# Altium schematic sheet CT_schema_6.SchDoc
size 479 x 328 mm
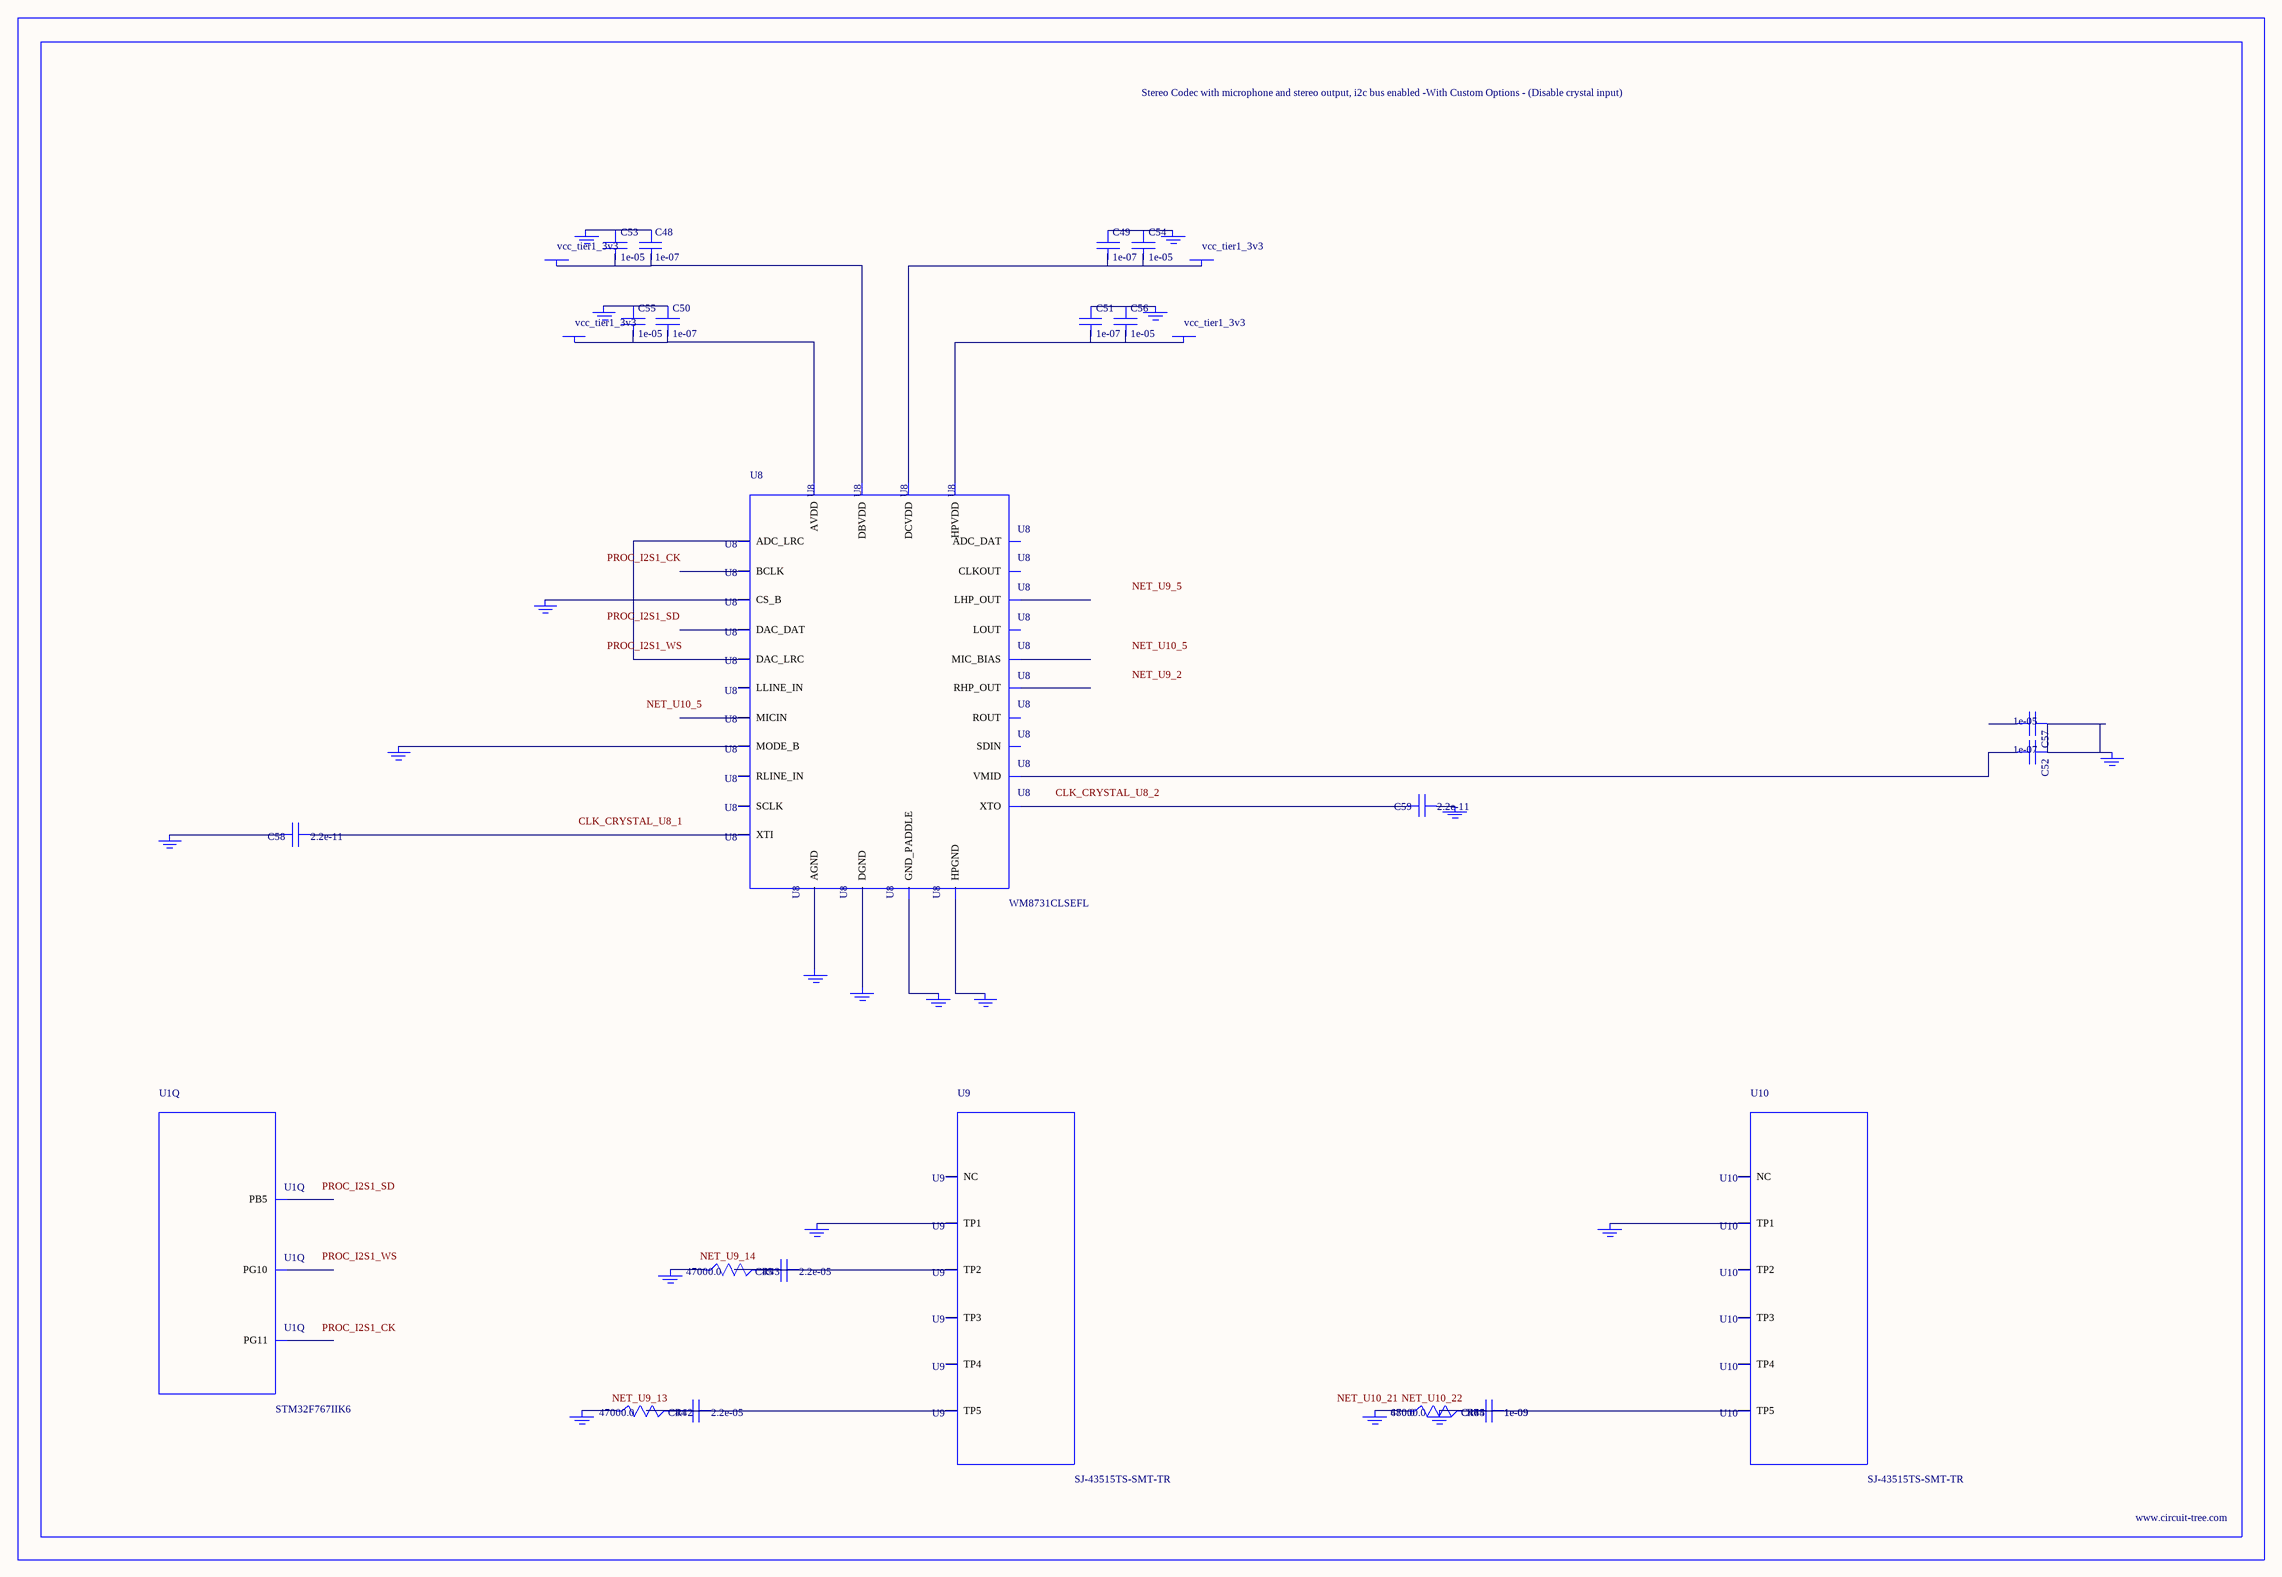
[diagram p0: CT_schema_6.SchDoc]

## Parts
BORDER5  (no value)
C44  2.2e-05  [C1210]
C45  2.2e-05  [C1210]
C46  1e-09  [C0402]
C47  1e-09  [C0402]
C48  1e-07  [C0402]
C49  1e-07  [C0402]
C50  1e-07  [C0402]
C51  1e-07  [C0402]
C52  1e-07  [C0402]
C53  1e-05  [C0805]
C54  1e-05  [C0805]
C55  1e-05  [C0805]
C56  1e-05  [C0805]
C57  1e-05  [C0805]
C58  2.2e-11  [C0402]
C59  2.2e-11  [C0402]
GND_INSTANCE_5_0  (no value)
GND_INSTANCE_5_1  (no value)
GND_INSTANCE_5_2  (no value)
GND_INSTANCE_5_3  (no value)
GND_INSTANCE_5_4  (no value)
GND_INSTANCE_5_5  (no value)
GND_INSTANCE_5_6  (no value)
GND_INSTANCE_5_7  (no value)
GND_INSTANCE_5_8  (no value)
GND_INSTANCE_5_9  (no value)
GND_INSTANCE_5_10  (no value)
GND_INSTANCE_5_11  (no value)
GND_INSTANCE_5_12  (no value)
GND_INSTANCE_5_13  (no value)
GND_INSTANCE_5_14  (no value)
GND_INSTANCE_5_15  (no value)
GND_INSTANCE_5_16  (no value)
GND_INSTANCE_5_17  (no value)
GND_INSTANCE_5_18  (no value)
POWER_INSTANCE_5_0  vcc_tier1_3v3
POWER_INSTANCE_5_1  vcc_tier1_3v3
POWER_INSTANCE_5_2  vcc_tier1_3v3
POWER_INSTANCE_5_3  vcc_tier1_3v3
R42  47000.0  [R0603]
R43  47000.0  [R0603]
R44  47000.0  [R0603]
R45  680.0  [R0603]
U1  STM32F767IIK6  [UFBGA176_25]  (part Q of 17)
U8  WM8731CLSEFL  [QFN-28]
U9  SJ-43515TS-SMT-TR  [SJ-43515TS-SMT-TR]
U10  SJ-43515TS-SMT-TR  [SJ-43515TS-SMT-TR]

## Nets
NetC44_1: C44.1 C44.2 R42.2 U9.5(TP5)
NetC45_1: C45.1 C45.2 R43.2 U9.2(TP2)
NetC46_1: C46.1 C46.2 C47.1 C47.2 GND_INSTANCE_5_18.0(GND) R44.2 R45.2 U10.5(TP5)
NetC48_1: C48.1 C53.1 GND_INSTANCE_5_3.0(GND)
NetC48_2: C48.2 C53.2 POWER_INSTANCE_5_1.0(PWR) U8.5(DBVDD)
NetC49_1: C49.1 C54.1 GND_INSTANCE_5_2.0(GND)
NetC49_2: C49.2 C54.2 POWER_INSTANCE_5_0.0(PWR) U8.3(DCVDD)
NetC50_1: C50.1 C55.1 GND_INSTANCE_5_6.0(GND)
NetC50_2: C50.2 C55.2 POWER_INSTANCE_5_3.0(PWR) U8.18(AVDD)
NetC51_1: C51.1 C56.1 GND_INSTANCE_5_4.0(GND)
NetC51_2: C51.2 C56.2 POWER_INSTANCE_5_2.0(PWR) U8.12(HPVDD)
NetC52_1: C52.1 C57.1 GND_INSTANCE_5_7.0(GND)
NetC52_2: C52.2 U8.20(VMID)
NetC58_1: C58.1 U8.1(XTI)
NetC58_2: C58.2 GND_INSTANCE_5_0.0(GND)
NetC59_1: C59.1 GND_INSTANCE_5_1.0(GND)
NetC59_2: C59.2 U8.2(XTO)
NetGND_INSTANCE_5_5_0: GND_INSTANCE_5_5.0(GND) U8.15(HPGND)
NetGND_INSTANCE_5_8_0: GND_INSTANCE_5_8.0(GND) U8.25(MODE_B)
NetGND_INSTANCE_5_9_0: GND_INSTANCE_5_9.0(GND) U8.26(CS_B)
NetGND_INSTANCE_5_10_0: GND_INSTANCE_5_10.0(GND) U8.29(GND_PADDLE)
NetGND_INSTANCE_5_11_0: GND_INSTANCE_5_11.0(GND) U8.4(DGND)
NetGND_INSTANCE_5_12_0: GND_INSTANCE_5_12.0(GND) U8.19(AGND)
NetGND_INSTANCE_5_13_0: GND_INSTANCE_5_13.0(GND) U9.1(TP1)
NetGND_INSTANCE_5_14_0: GND_INSTANCE_5_14.0(GND) R43.1
NetGND_INSTANCE_5_15_0: GND_INSTANCE_5_15.0(GND) R42.1
NetGND_INSTANCE_5_16_0: GND_INSTANCE_5_16.0(GND) U10.1(TP1)
NetGND_INSTANCE_5_17_0: GND_INSTANCE_5_17.0(GND) R44.1 R45.1
NetU8_9: U8.9(DAC_LRC) U8.11(ADC_LRC)

Not connected (* = marked no-connect by the designer): C57 2; U1 A6(PB5) B9(PG11) B10(PG10); U8 6(CLKOUT) 7(BCLK) 8(DAC_DAT) 10(ADC_DAT) 13(LHP_OUT) 14(RHP_OUT) 16(LOUT) 17(ROUT) 21(MIC_BIAS) 22(MICIN) 23(RLINE_IN) 24(LLINE_IN) 27(SDIN) 28(SCLK); U9 3(TP3) 4(TP4) 6(NC); U10 2(TP2) 3(TP3) 4(TP4) 6(NC)

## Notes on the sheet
- Labels drawn without touching a wire or pin: CLK_CRYSTAL_U8_1, CLK_CRYSTAL_U8_2, NET_U9_2, NET_U9_5, NET_U9_13, NET_U9_14, NET_U10_5, NET_U10_21, NET_U10_22, PROC_I2S1_CK, PROC_I2S1_SD, PROC_I2S1_WS

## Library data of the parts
BORDER5 = BORDER_PAGE5
C44 C45 = C1210C224K5RACTU
C46 C47 = C0402C102K3RAC
C48-C52 = C0402C104K3RACTU
C53-C57 = C0805C106K8RACTU
C58 C59 = C0402C220K3RAC
GND_INSTANCE_5_0-GND_INSTANCE_5_18 = GND
POWER_INSTANCE_5_0-POWER_INSTANCE_5_3 = PWR
R42-R44 = RC0603JR-0747KL
R45 = RC0603JR-07680RL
